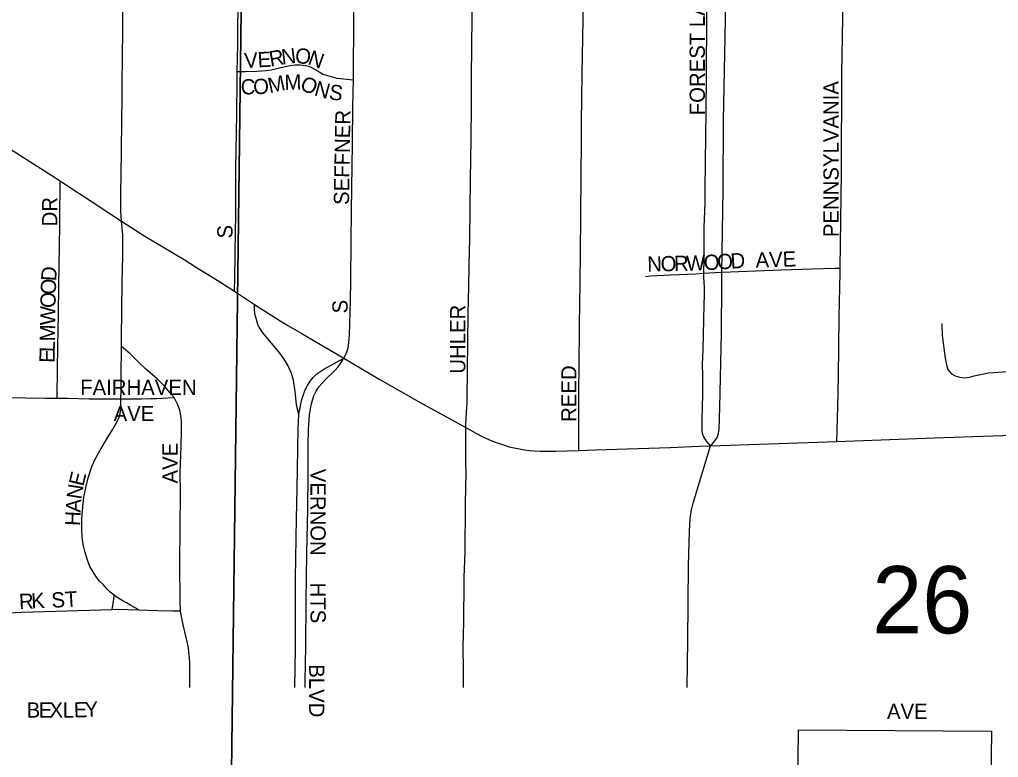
# Model space of a CAD drawing. Extents: x -9.1 to 34, y -3.1 to 22.
# Drawn here: x 6.099 to 6.709, y 19.215 to 19.674 of the extents above; entities that cross this region are included whole.
import ezdxf

# ---------------------------------------------------------------- set-up
doc = ezdxf.new("R2010")
doc.units = 0
for name, color, linetype in [('GM_X_City_Street', 7, 'Continuous'), ('GM_X_City_Street_Text', 7, 'Continuous'), ('GM_X_Corporation', 7, 'Continuous'), ('GM_X_Section', 7, 'Continuous'), ('GM_X_Section_Text', 7, 'Continuous'), ('GM_X_State_Route', 7, 'Continuous')]:
    doc.layers.add(name, color=color, linetype=linetype)

msp = doc.modelspace()

# ---------------------------------------------------------------- linework, layer by layer
at = {"layer": 'GM_X_City_Street'}
for points in [[(6.16242, 19.54826), (6.16199, 19.55458), (6.16193, 19.5558), (6.16192, 19.55698), (6.16207, 19.56407), (6.16226, 19.57953), (6.16238, 19.58956), (6.16248, 19.59828), (6.16255, 19.60452), (6.16266, 19.61373), (6.16276, 19.62261), (6.16291, 19.6352), (6.16304, 19.64859), (6.16324, 19.66915), (6.16343, 19.68872), (6.16367, 19.71289), (6.16383, 19.72999), (6.16402, 19.74959), (6.16417, 19.76506)], [(6.23449, 19.64157), (6.23478, 19.65805), (6.23479, 19.66424), (6.23498, 19.68576), (6.23521, 19.70433), (6.23581, 19.73206), (6.23595, 19.74728), (6.23597, 19.76159), (6.23594, 19.76488)], [(6.30681, 19.63638), (6.30685, 19.64068), (6.30719, 19.67229), (6.30733, 19.69405), (6.30749, 19.70959), (6.30811, 19.74064), (6.3084, 19.76145)], [(6.37683, 19.41986), (6.37696, 19.42225), (6.37756, 19.43282), (6.37771, 19.43498), (6.37775, 19.43845), (6.37829, 19.49072), (6.37873, 19.50781), (6.37899, 19.52114), (6.37931, 19.53758), (6.37987, 19.5738), (6.38007, 19.58741), (6.38024, 19.59875), (6.38034, 19.62045), (6.38045, 19.63772), (6.38057, 19.65741), (6.38079, 19.67521), (6.38106, 19.69625), (6.38123, 19.7104), (6.38154, 19.73507), (6.38183, 19.75778)], [(6.44723, 19.40568), (6.44725, 19.41237), (6.44727, 19.42388), (6.44728, 19.43358), (6.4473, 19.44542), (6.44741, 19.45545), (6.44772, 19.4845), (6.44784, 19.49607), (6.448, 19.51087), (6.4482, 19.52829), (6.44845, 19.55165), (6.44873, 19.57746), (6.44886, 19.59703), (6.44901, 19.61002), (6.44918, 19.62465), (6.44935, 19.63979), (6.44999, 19.67386), (6.44993, 19.68629), (6.45005, 19.69388), (6.45033, 19.71131), (6.45052, 19.72331), (6.45063, 19.73022), (6.45092, 19.74857), (6.45106, 19.7546)], [(6.52515, 19.51595), (6.52523, 19.52482), (6.52533, 19.53518), (6.52533, 19.54445), (6.52588, 19.55982), (6.52588, 19.56774), (6.5261, 19.58501), (6.5263, 19.60128), (6.5265, 19.61658), (6.52655, 19.62052), (6.52672, 19.63405), (6.5268, 19.64716), (6.52694, 19.66722), (6.527, 19.67738), (6.52701, 19.69468), (6.52702, 19.70209), (6.52704, 19.71135), (6.52764, 19.74235), (6.52779, 19.75141)], [(6.53628, 19.5166), (6.53712, 19.56792), (6.53743, 19.61125), (6.53861, 19.67318), (6.53927, 19.70715), (6.53949, 19.73807), (6.53954, 19.75075)], [(6.61008, 19.51918), (6.61083, 19.5784), (6.61114, 19.6405), (6.6116, 19.67463), (6.61174, 19.68696), (6.61183, 19.69922), (6.61209, 19.71775), (6.61244, 19.74731)], [(6.23449, 19.64157), (6.23956, 19.64159), (6.2466, 19.64163), (6.25258, 19.64207), (6.25554, 19.64251), (6.26441, 19.64471), (6.26748, 19.64528), (6.27059, 19.64561), (6.27375, 19.6457), (6.27694, 19.64531), (6.28002, 19.64432), (6.28542, 19.64124), (6.28804, 19.63993), (6.29081, 19.63892), (6.29659, 19.63744), (6.30681, 19.63638)], [(6.23272, 19.50479), (6.23292, 19.51324), (6.23321, 19.5262), (6.23325, 19.52891), (6.23364, 19.55301), (6.23359, 19.56537), (6.23368, 19.58083), (6.23428, 19.61487), (6.23445, 19.63567), (6.23449, 19.64157)], [(6.30086, 19.46305), (6.3021, 19.46533), (6.30266, 19.46698), (6.3035, 19.46946), (6.30395, 19.4726), (6.3045, 19.47767), (6.30504, 19.49871), (6.30515, 19.51138), (6.30538, 19.53588), (6.30571, 19.55463), (6.30597, 19.56894), (6.30626, 19.59639), (6.30651, 19.61998), (6.30681, 19.63638)], [(6.12228, 19.43819), (6.12231, 19.44036), (6.12267, 19.47091), (6.12286, 19.48047), (6.12313, 19.49036), (6.12348, 19.50857), (6.12379, 19.53321), (6.12394, 19.54571), (6.12397, 19.55582), (6.12415, 19.56707), (6.12425, 19.57345)], [(6.16237, 19.47042), (6.16241, 19.47523), (6.1626, 19.49304), (6.16278, 19.51066), (6.16315, 19.5266), (6.16327, 19.53753), (6.16322, 19.53885), (6.16316, 19.53982), (6.16242, 19.54826)], [(6.48875, 19.5139), (6.49185, 19.51435), (6.50437, 19.51503), (6.52001, 19.51564), (6.52515, 19.51595)], [(6.52921, 19.40847), (6.52683, 19.41134), (6.52504, 19.41418), (6.52435, 19.41594), (6.52397, 19.41859), (6.52409, 19.42504), (6.52446, 19.44052), (6.5244, 19.45263), (6.52436, 19.45905), (6.52462, 19.46858), (6.52512, 19.48697), (6.52541, 19.49625), (6.52548, 19.50254), (6.52549, 19.50515), (6.52543, 19.5072), (6.52517, 19.51352), (6.52515, 19.51595)], [(6.52515, 19.51595), (6.53566, 19.51658), (6.53628, 19.5166)], [(6.52921, 19.40847), (6.52988, 19.40923), (6.53116, 19.41069), (6.53321, 19.41335), (6.53409, 19.4154), (6.53468, 19.41859), (6.53501, 19.43251), (6.53611, 19.47869), (6.53625, 19.50949), (6.53628, 19.5166)], [(6.53628, 19.5166), (6.55758, 19.51752), (6.57324, 19.51809), (6.5923, 19.51865), (6.60678, 19.51908), (6.61008, 19.51918)], [(6.60794, 19.41127), (6.60814, 19.41821), (6.60855, 19.43292), (6.60897, 19.45173), (6.60947, 19.48889), (6.61005, 19.51633), (6.61008, 19.51918)], [(6.2729, 19.42817), (6.27216, 19.43043), (6.27181, 19.43228), (6.27145, 19.43418), (6.27052, 19.44226), (6.26958, 19.44938), (6.26821, 19.45359), (6.26611, 19.45829), (6.26363, 19.4625), (6.26041, 19.46707), (6.25261, 19.47636), (6.25009, 19.47945), (6.24858, 19.48184), (6.24754, 19.48348), (6.24623, 19.48779), (6.24554, 19.49074), (6.24526, 19.49363), (6.24518, 19.49643)], [(6.67339, 19.48472), (6.67356, 19.47717), (6.67537, 19.46307), (6.67618, 19.45893), (6.67717, 19.45608), (6.67809, 19.45477), (6.67946, 19.45329), (6.68161, 19.45217), (6.68452, 19.45117), (6.68757, 19.45083), (6.69053, 19.45124), (6.69345, 19.45202), (6.6964, 19.4528), (6.70244, 19.45394), (6.7147, 19.45473), (6.7328, 19.45557), (6.74146, 19.45603)], [(6.16204, 19.43774), (6.16223, 19.44318), (6.16223, 19.45217), (6.16237, 19.47042)], [(6.19511, 19.43857), (6.19364, 19.44047), (6.18956, 19.44517), (6.18461, 19.45025), (6.17755, 19.45618), (6.17371, 19.46002), (6.16773, 19.46568), (6.16488, 19.4682), (6.16237, 19.47042)], [(6.2729, 19.42817), (6.274, 19.43443), (6.27474, 19.43743), (6.27569, 19.44039), (6.27683, 19.44328), (6.27818, 19.44606), (6.27982, 19.44869), (6.28176, 19.4511), (6.28397, 19.45328), (6.28841, 19.45621), (6.29253, 19.45847), (6.30086, 19.46305)], [(6.27685, 19.25808), (6.2769, 19.26198), (6.27723, 19.28366), (6.27751, 19.31181), (6.27769, 19.32682), (6.2779, 19.34186), (6.27846, 19.36898), (6.27865, 19.39067), (6.27873, 19.40924), (6.27882, 19.41861), (6.27953, 19.42782), (6.2805, 19.4339), (6.28127, 19.43685), (6.2823, 19.43973), (6.28363, 19.44253), (6.28531, 19.44514), (6.2873, 19.44753), (6.28933, 19.44952), (6.29551, 19.45565), (6.29707, 19.45754), (6.29835, 19.45909), (6.30086, 19.46305)], [(6.08491, 19.43871), (6.09069, 19.4386), (6.10292, 19.43838), (6.11499, 19.43829), (6.12228, 19.43819)], [(6.12228, 19.43819), (6.12868, 19.43811), (6.14224, 19.43786), (6.16204, 19.43774)], [(6.15777, 19.31562), (6.15543, 19.31749), (6.15321, 19.3196), (6.15112, 19.32191), (6.14858, 19.32451), (6.14652, 19.32733), (6.14427, 19.3307), (6.14276, 19.33351), (6.14127, 19.33726), (6.13976, 19.34214), (6.13864, 19.34626), (6.13807, 19.34982), (6.13788, 19.35226), (6.1377, 19.35619), (6.1377, 19.36294), (6.13826, 19.37063), (6.139, 19.37663), (6.14031, 19.38338), (6.14163, 19.38862), (6.14387, 19.39556), (6.14612, 19.40062), (6.14912, 19.40587), (6.15436, 19.41449), (6.15699, 19.41881), (6.15868, 19.42181), (6.16017, 19.42443), (6.1613, 19.42743), (6.16205, 19.43136), (6.16205, 19.43399), (6.16204, 19.43774)], [(6.16204, 19.43774), (6.16992, 19.43774), (6.17479, 19.43775), (6.1806, 19.43793), (6.18435, 19.43793), (6.18754, 19.43812), (6.19511, 19.43857)], [(6.19922, 19.30588), (6.199, 19.31152), (6.19874, 19.33553), (6.19886, 19.35743), (6.19913, 19.37898), (6.19898, 19.39196), (6.19947, 19.40805), (6.19984, 19.41795), (6.19971, 19.42364), (6.19946, 19.42736), (6.19872, 19.43082), (6.19736, 19.43453), (6.19511, 19.43857)], [(6.27032, 19.25808), (6.27068, 19.28263), (6.27086, 19.32602), (6.27131, 19.36321), (6.27154, 19.37248), (6.27177, 19.38177), (6.27251, 19.419), (6.2729, 19.42817)], [(6.37536, 19.25808), (6.37538, 19.2627), (6.3754, 19.26859), (6.37534, 19.2716), (6.37527, 19.28086), (6.37544, 19.29328), (6.37553, 19.29618), (6.37593, 19.32688), (6.3765, 19.34237), (6.37644, 19.35169), (6.37662, 19.3624), (6.37671, 19.37284), (6.37701, 19.39152), (6.37688, 19.39747), (6.37688, 19.40044), (6.37688, 19.40311), (6.37683, 19.41986)], [(6.51475, 19.25808), (6.51475, 19.25846), (6.51524, 19.28716), (6.5156, 19.33395), (6.51622, 19.35536), (6.51659, 19.3634), (6.51745, 19.3686), (6.51844, 19.37293), (6.52175, 19.38378), (6.52921, 19.40847)], [(6.15661, 19.30672), (6.15699, 19.30897), (6.1575, 19.31195), (6.15758, 19.31289), (6.15777, 19.31562)], [(6.1732, 19.30636), (6.16826, 19.30922), (6.1656, 19.31076), (6.1629, 19.3123), (6.15919, 19.31455), (6.15777, 19.31562)], [(6.0826, 19.30403), (6.08786, 19.30432), (6.10042, 19.30504), (6.15661, 19.30672)], [(6.15661, 19.30672), (6.15976, 19.30682), (6.1732, 19.30636)], [(6.1732, 19.30636), (6.185, 19.30596), (6.1944, 19.30591), (6.19922, 19.30588)], [(6.20496, 19.25808), (6.20497, 19.26448), (6.20492, 19.27378), (6.20407, 19.28281), (6.20296, 19.2885), (6.20085, 19.29704), (6.19925, 19.30534), (6.19922, 19.30588)]]:
    msp.add_lwpolyline(points, dxfattribs=at)
at = {"layer": 'GM_X_Corporation'}
msp.add_lwpolyline([(6.58198, 19.04271), (6.58411, 19.23174), (6.70434, 19.23095), (6.70102, 18.96926)], dxfattribs=at)
at = {"layer": 'GM_X_Section'}
for points in [[(5.226, 19.77229), (6.2379, 19.76083), (6.22532, 18.76489), (5.22068, 18.771)], [(6.2379, 19.76083), (7.24082, 19.71069), (7.22846, 18.75339), (6.22532, 18.76489)]]:
    msp.add_lwpolyline(points, close=True, dxfattribs=at)
at = {"layer": 'GM_X_State_Route'}
for points in [[(6.08608, 19.59768), (6.10065, 19.58839), (6.11908, 19.57685), (6.12425, 19.57345), (6.12693, 19.57169), (6.14417, 19.56042), (6.15568, 19.55263), (6.16242, 19.54826), (6.17702, 19.53896), (6.2014, 19.52441), (6.20856, 19.51993), (6.21963, 19.51299), (6.23272, 19.50479)], [(6.23272, 19.50479), (6.24518, 19.49643), (6.25596, 19.4897), (6.26131, 19.48636), (6.2664, 19.4833), (6.27469, 19.47847), (6.28283, 19.47363), (6.30086, 19.46305), (6.32329, 19.44978), (6.35034, 19.43443), (6.37683, 19.41986), (6.38305, 19.41645), (6.38753, 19.41418), (6.39171, 19.41222), (6.39517, 19.41075), (6.39775, 19.40988), (6.4009, 19.40884), (6.40396, 19.408), (6.40701, 19.40719), (6.41031, 19.4066), (6.41351, 19.40604), (6.41669, 19.40566), (6.41937, 19.40541), (6.42313, 19.40517), (6.43268, 19.4051), (6.44723, 19.40568), (6.4576, 19.40609), (6.5041, 19.40758), (6.52221, 19.40822)], [(6.52221, 19.40822), (6.52921, 19.40847), (6.60794, 19.41127), (6.66854, 19.41343), (6.74193, 19.41591), (6.76786, 19.41674), (6.81536, 19.41831), (6.85163, 19.4195), (6.89105, 19.42097), (6.9106, 19.4217), (6.94467, 19.42279), (6.98225, 19.42377), (6.98655, 19.42384)]]:
    msp.add_lwpolyline(points, dxfattribs=at)

# ---------------------------------------------------------------- texts
at = {"layer": 'GM_X_City_Street_Text'}
for s, height, rotation, p in [('FOREST LAWN BLVD', 0.0094697, 90, (6.52573, 19.61426)), ('N', 0.00947, 6.92438, (6.26248, 19.64581)), ('O', 0.00947, 354.90056, (6.27023, 19.64681)), ('V', 0.00947, 3.45501, (6.23911, 19.64354)), ('E', 0.00947, 3.44509, (6.24743, 19.64404)), ('R', 0.00947, 9.67663, (6.2552, 19.64457)), ('N', 0.00947, 339.94782, (6.27789, 19.64621)), ('O', 0.00947, 2.56341, (6.24462, 19.62727)), ('M', 0.00947, 12.59039, (6.25474, 19.62788)), ('M', 0.00947, 1.62149, (6.26403, 19.63)), ('O', 0.00947, 337.00519, (6.27297, 19.63048)), ('C', 0.00947, 0.09715, (6.23668, 19.62725)), ('N', 0.00947, 344.62359, (6.28194, 19.62677)), ('S', 0.00947, 351.48737, (6.29119, 19.62431)), ('PENNSYLVANIA', 0.0094697, 90, (6.60906, 19.53842)), ('SEFFNER', 0.00947, 89.03135, (6.30406, 19.55838)), ('DR', 0.00947, 90, (6.1224, 19.54509)), ('S', 0.00947, 90, (6.23156, 19.53759)), ('W', 0.00947, 1.61234, (6.51417, 19.51746)), ('O', 0.00947, 3.23002, (6.5253, 19.51778)), ('O', 0.00947, 3.5684, (6.53367, 19.51825)), ('D', 0.00947, 3.56542, (6.54199, 19.51877)), ('AVE', 0.00947, 1.90818, (6.55745, 19.51937)), ('N', 0.00947, 1.37693, (6.48997, 19.51687)), ('O', 0.00947, 1.4012, (6.4983, 19.51707)), ('R', 0.00947, 1.38416, (6.50663, 19.51728)), ('D', 0.00947, 86.785, (6.12172, 19.51085)), ('O', 0.00947, 88.2292, (6.12147, 19.50258)), ('O', 0.00947, 89.00188, (6.12132, 19.49429)), ('S', 0.00947, 90, (6.30323, 19.49092)), ('W', 0.00947, 88.99626, (6.12113, 19.48345)), ('UHLER', 0.00947, 90, (6.37656, 19.45342)), ('M', 0.00947, 88.9981, (6.12096, 19.47346)), ('L', 0.00947, 89.02791, (6.12084, 19.46679)), ('E', 0.00947, 88.98915, (6.12073, 19.46012)), ('REED', 0.00947, 90, (6.44573, 19.42342)), ('FAIRHAVEN', 0.00947, 0.00001, (6.13668, 19.4402)), ('AVE', 0.00947, 0.00001, (6.15751, 19.42391)), ('AVE', 0.00947, 90, (6.1974, 19.38509)), ('VERNON', 0.00947, 270, (6.28012, 19.39426)), ('E', 0.00947, 76.76573, (6.13867, 19.38292)), ('N', 0.00947, 81.28873, (6.13745, 19.37488)), ('A', 0.00947, 86.85151, (6.13702, 19.3668)), ('H', 0.00947, 86.85048, (6.13656, 19.35848)), ('HTS', 0.00947, 270, (6.28012, 19.32342)), ('R', 0.00947, 2.28536, (6.09875, 19.30693)), ('K', 0.00947, 3.17297, (6.10641, 19.30723)), ('ST', 0.00947, 3.57463, (6.11907, 19.3077)), ('BLVD', 0.00947, 270, (6.27929, 19.27259)), ('B', 0.00947, 0.02429, (6.10334, 19.23937)), ('E', 0.00947, 0.02732, (6.11084, 19.23937)), ('X', 0.00947, 0.02186, (6.11751, 19.23938)), ('L', 0.00947, 0.18486, (6.12587, 19.23938)), ('E', 0.00947, 1.92423, (6.13284, 19.23941)), ('Y', 0.00947, 3.12784, (6.13972, 19.23964)), ('AVE', 0.00947, 0.00001, (6.63918, 19.23854))]:
    msp.add_text(s, height=height, rotation=rotation, dxfattribs=at).set_placement(p)
at = {"layer": 'GM_X_Section_Text'}
msp.add_text('26', height=0.041856, rotation=0.00001, dxfattribs=at).set_placement((6.63001, 19.29181))

doc.saveas('drawing.dxf')
